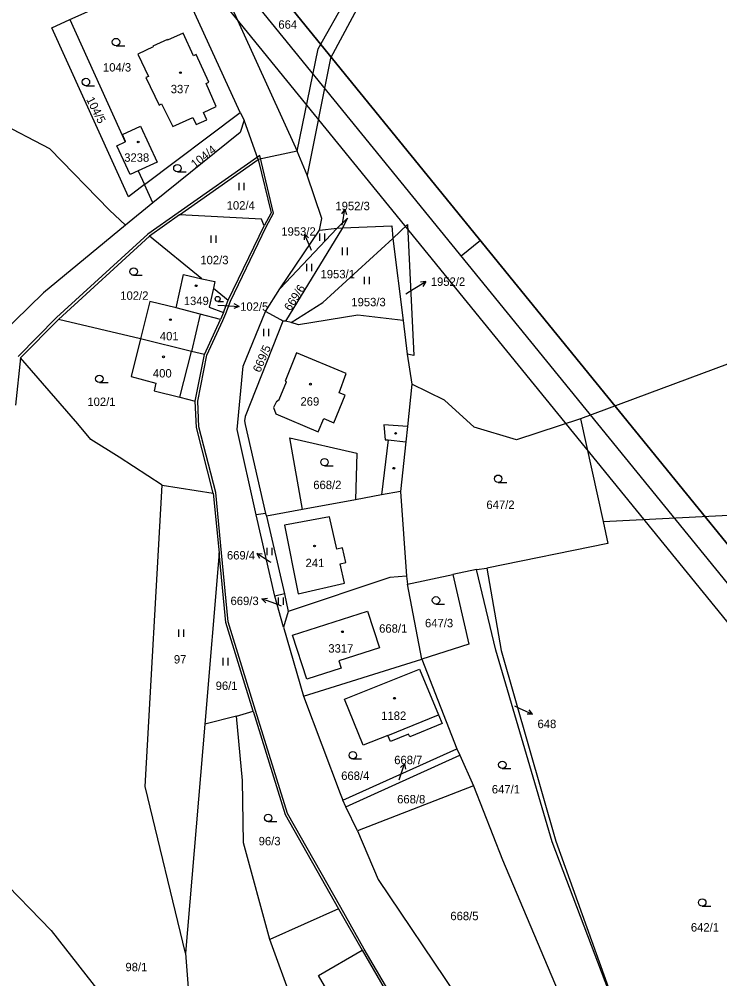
# Model space of a CAD drawing. Extents: x -866656 to -858817, y -1041816 to -1038653.
# Drawn here: x -866089.1 to -865947.5, y -1039508.8 to -1039314.8 of the extents above; entities that cross this region are included whole.
import ezdxf

# ---------------------------------------------------------------- set-up
doc = ezdxf.new("R2010")
doc.units = 0
for name, color, linetype in [('Hranice parcel', 7, 'Continuous'), ('Parcelní čísla', 7, 'Continuous'), ('Pop  PČ popisy', 7, 'Continuous'), ('tisk ramy', 7, 'Continuous'), ('Vnitřní kresba', 7, 'Continuous'), ('Značky budov', 7, 'Continuous'), ('Značky kultur', 7, 'Continuous')]:
    doc.layers.add(name, color=color, linetype=linetype)

msp = doc.modelspace()

# ---------------------------------------------------------------- linework, layer by layer
at = {"layer": 'Hranice parcel'}
for p, q in [((-866028.64, -1039320.79), (-866017.02, -1039299.91)), ((-866078.86, -1039314.87), (-866057.44, -1039305.25)), ((-866044.44, -1039333.64), (-866057.44, -1039305.25)), ((-866048.15, -1039307.93), (-866032.91, -1039341.46)), ((-866019.82, -1039310.81), (-866026.21, -1039322.66)), ((-866082.5, -1039316.53), (-866078.86, -1039314.87)), ((-866078.86, -1039314.87), (-866067.68, -1039339.57)), ((-866067.02, -1039350.71), (-866082.5, -1039316.53)), ((-866059.15, -1039318.92), (-866062.06, -1039320.26)), ((-866059.09, -1039319.05), (-866059.15, -1039318.92)), ((-866055.96, -1039317.6), (-866059.09, -1039319.05)), ((-866053.86, -1039322.16), (-866055.96, -1039317.6)), ((-866061.99, -1039320.4), (-866065.14, -1039321.86)), ((-866062.06, -1039320.26), (-866061.99, -1039320.4)), ((-866032.91, -1039341.46), (-866028.64, -1039320.79)), ((-866065.14, -1039321.86), (-866062.98, -1039326.34)), ((-866053.32, -1039321.92), (-866053.86, -1039322.16)), ((-866050.74, -1039327.52), (-866053.32, -1039321.92)), ((-866026.21, -1039322.66), (-866030.88, -1039346.29)), ((-866062.98, -1039326.34), (-866063.51, -1039326.6)), ((-866063.51, -1039326.6), (-866060.83, -1039332.14)), ((-866051.28, -1039327.77), (-866050.74, -1039327.52)), ((-866049.3, -1039332.42), (-866051.28, -1039327.77)), ((-866082.88, -1039340.97), (-866099.79, -1039332.19)), ((-866060.83, -1039332.14), (-866060.3, -1039331.89)), ((-866060.3, -1039331.89), (-866058.07, -1039336.5)), ((-866051.86, -1039333.68), (-866049.3, -1039332.42)), ((-866063.75, -1039348.24), (-866044.44, -1039333.64)), ((-866051.2, -1039335.12), (-866051.86, -1039333.68)), ((-866044.44, -1039333.64), (-866043.63, -1039335.22)), ((-866058.07, -1039336.5), (-866054, -1039334.65)), ((-866054, -1039334.65), (-866053.34, -1039336.09)), ((-866053.34, -1039336.09), (-866051.2, -1039335.12)), ((-866043.63, -1039335.22), (-866044.44, -1039337.67)), ((-866040.79, -1039343.17), (-866043.63, -1039335.22)), ((-866068.24, -1039338.11), (-866064.58, -1039336.41)), ((-866067.58, -1039339.52), (-866068.24, -1039338.11)), ((-866064.58, -1039336.41), (-866061.23, -1039343.66)), ((-866044.44, -1039337.67), (-866062.09, -1039351.91)), ((-866069.37, -1039340.37), (-866067.68, -1039339.57)), ((-866067.68, -1039339.57), (-866067.58, -1039339.52)), ((-866070.83, -1039353.37), (-866082.88, -1039340.97)), ((-866066.66, -1039346.2), (-866069.37, -1039340.37)), ((-866032.91, -1039341.46), (-866040.79, -1039343.17)), ((-866030.88, -1039346.29), (-866032.91, -1039341.46)), ((-866061.23, -1039343.66), (-866065.02, -1039345.43)), ((-866056.68, -1039354.36), (-866040.79, -1039343.17)), ((-866040.79, -1039343.17), (-866038.2, -1039353.94)), ((-866065.02, -1039345.43), (-866066.66, -1039346.2)), ((-866065.02, -1039345.43), (-866063.75, -1039348.24)), ((-866027.92, -1039355.11), (-866030.88, -1039346.29)), ((-866063.75, -1039348.24), (-866067.02, -1039350.71)), ((-866062.09, -1039351.91), (-866063.75, -1039348.24)), ((-866062.09, -1039351.91), (-866067.64, -1039356.45)), ((-866067.64, -1039356.45), (-866070.83, -1039353.37)), ((-866056.68, -1039354.36), (-866062.78, -1039358.65)), ((-866040.12, -1039355.21), (-866056.68, -1039354.36)), ((-866039.6, -1039356.54), (-866040.12, -1039355.21)), ((-866038.2, -1039353.94), (-866039.6, -1039356.54)), ((-866028.42, -1039357.43), (-866027.92, -1039355.11)), ((-866024.83, -1039357.02), (-866022.74, -1039355.04)), ((-866022.74, -1039355.04), (-866023.78, -1039356.97)), ((-866067.64, -1039356.45), (-866084.17, -1039370.09)), ((-866046.85, -1039371.6), (-866039.6, -1039356.54)), ((-866036.43, -1039369.33), (-866024.83, -1039357.02)), ((-866036.43, -1039369.33), (-866028.42, -1039357.43)), ((-866023.78, -1039356.97), (-866035.26, -1039375.83)), ((-866028.42, -1039357.43), (-866024.83, -1039357.02)), ((-866024.83, -1039357.02), (-866023.78, -1039356.97)), ((-866023.78, -1039356.97), (-866013.77, -1039356.58)), ((-866013.77, -1039356.58), (-866013.6, -1039359.13)), ((-866013.6, -1039359.13), (-866010.65, -1039356.31)), ((-866010.65, -1039356.31), (-866009.31, -1039382.79)), ((-866062.78, -1039358.65), (-866081.18, -1039375.48)), ((-866052.2, -1039367.25), (-866062.78, -1039358.65)), ((-866027.74, -1039372.07), (-866013.6, -1039359.13)), ((-866013.6, -1039359.13), (-866011.48, -1039375.7)), ((-866057.39, -1039373.14), (-866055.87, -1039366.42)), ((-866055.87, -1039366.42), (-866052.2, -1039367.25)), ((-866052.2, -1039367.25), (-866049.54, -1039367.85)), ((-866049.84, -1039369.17), (-866050.71, -1039373.02)), ((-866049.54, -1039367.85), (-866049.84, -1039369.17)), ((-866049.84, -1039369.17), (-866046.85, -1039371.6)), ((-866039.34, -1039373.88), (-866036.43, -1039369.33)), ((-866084.17, -1039370.09), (-866092.99, -1039378.67)), ((-866062.69, -1039371.86), (-866064.59, -1039379.4)), ((-866057.39, -1039373.14), (-866062.69, -1039371.86)), ((-866052.54, -1039374.42), (-866057.39, -1039373.14)), ((-866050.71, -1039373.02), (-866047.83, -1039374.11)), ((-866047.83, -1039374.11), (-866046.85, -1039371.6)), ((-866034.12, -1039376.14), (-866027.74, -1039372.07)), ((-866048.39, -1039375.52), (-866052.54, -1039374.42)), ((-866047.83, -1039374.11), (-866048.39, -1039375.52)), ((-866043.85, -1039384.96), (-866039.34, -1039373.88)), ((-866036.22, -1039375.56), (-866039.34, -1039373.88)), ((-866020.66, -1039374.6), (-866032.67, -1039376.55)), ((-866011.48, -1039375.7), (-866020.66, -1039374.6)), ((-866081.18, -1039375.48), (-866088.85, -1039383.25)), ((-866064.59, -1039379.4), (-866081.18, -1039375.48)), ((-866051.65, -1039382.56), (-866048.39, -1039375.52)), ((-866035.78, -1039375.84), (-866043.4, -1039395.11)), ((-866035.78, -1039375.84), (-866036.22, -1039375.56)), ((-866035.26, -1039375.83), (-866035.78, -1039375.84)), ((-866034.12, -1039376.14), (-866035.26, -1039375.83)), ((-866032.67, -1039376.55), (-866034.12, -1039376.14)), ((-866011.48, -1039375.7), (-866010.7, -1039382.53)), ((-865926.41, -1039377.21), (-865975.66, -1039395.58)), ((-866064.59, -1039379.4), (-866066.46, -1039387.06)), ((-866054.3, -1039382), (-866064.59, -1039379.4)), ((-866051.65, -1039382.56), (-866054.3, -1039382)), ((-866053.52, -1039392), (-866051.65, -1039382.56)), ((-866010.7, -1039382.53), (-866009.76, -1039388.61)), ((-866009.31, -1039382.79), (-866010.7, -1039382.53)), ((-866088.85, -1039383.25), (-866089.81, -1039392.85)), ((-866077.27, -1039396.58), (-866088.85, -1039383.25)), ((-866045.07, -1039397.73), (-866043.85, -1039384.96)), ((-866066.46, -1039387.06), (-866061.45, -1039388.35)), ((-866061.45, -1039388.35), (-866061.84, -1039389.95)), ((-866009.76, -1039388.61), (-866010.64, -1039397.17)), ((-866003.13, -1039391.81), (-866009.76, -1039388.61)), ((-866061.84, -1039389.95), (-866056.6, -1039391.24)), ((-866056.6, -1039391.24), (-866053.52, -1039392)), ((-866053.28, -1039397.31), (-866053.52, -1039392)), ((-865997.15, -1039397.26), (-866003.13, -1039391.81)), ((-866043.4, -1039395.11), (-866043.53, -1039396.02)), ((-866043.53, -1039396.02), (-866043.42, -1039396.72)), ((-865975.66, -1039395.58), (-865988.57, -1039399.82)), ((-865975.66, -1039395.58), (-865971.07, -1039416.36)), ((-866074.59, -1039399.75), (-866077.27, -1039396.58)), ((-866049.86, -1039410.61), (-866053.28, -1039397.31)), ((-866041.17, -1039415.01), (-866045.07, -1039397.73)), ((-866043.42, -1039396.72), (-866039.34, -1039414.72)), ((-866010.64, -1039397.17), (-866010.96, -1039400.24)), ((-865988.57, -1039399.82), (-865997.15, -1039397.26)), ((-866068.91, -1039403.37), (-866074.59, -1039399.75)), ((-866031.82, -1039413.91), (-866034.38, -1039399.43)), ((-866034.38, -1039399.43), (-866020.85, -1039402.53)), ((-866010.96, -1039400.24), (-866012, -1039410.29)), ((-866060.2, -1039409.03), (-866068.91, -1039403.37)), ((-866020.85, -1039402.53), (-866021.15, -1039411.96)), ((-866063.61, -1039469.96), (-866060.2, -1039409.03)), ((-866060.2, -1039409.03), (-866049.86, -1039410.61)), ((-866049.86, -1039410.61), (-866048.7, -1039422.71)), ((-866021.15, -1039411.96), (-866031.82, -1039413.91)), ((-866015.86, -1039410.99), (-866021.15, -1039411.96)), ((-866012, -1039410.29), (-866015.86, -1039410.99)), ((-866012, -1039410.29), (-866010.83, -1039427.42)), ((-866031.82, -1039413.91), (-866039.14, -1039415.25)), ((-866039.34, -1039414.72), (-866041.17, -1039415.01)), ((-866037.45, -1039431.46), (-866041.17, -1039415.01)), ((-866039.34, -1039414.72), (-866039.14, -1039415.25)), ((-866039.14, -1039415.25), (-866035.5, -1039431)), ((-865971.07, -1039416.36), (-865942.36, -1039414.92)), ((-865971.07, -1039416.36), (-865970.13, -1039420.81)), ((-865970.13, -1039420.81), (-865994.6, -1039425.76)), ((-866048.7, -1039422.71), (-866051.6, -1039457.36)), ((-866047.36, -1039436.76), (-866048.7, -1039422.71)), ((-866010.83, -1039427.42), (-866014.16, -1039427.65)), ((-866010.83, -1039427.42), (-866010.62, -1039428.99)), ((-866010.62, -1039428.99), (-866001.47, -1039427.05)), ((-865996.64, -1039426.09), (-866001.47, -1039427.05)), ((-866001.47, -1039427.05), (-865998.21, -1039441.16)), ((-865996.64, -1039426.09), (-865994.6, -1039425.76)), ((-865992.79, -1039442.34), (-865996.64, -1039426.09)), ((-865994.6, -1039425.76), (-865991.69, -1039442.44)), ((-866014.16, -1039427.65), (-866034.75, -1039434.55)), ((-866007.74, -1039444.16), (-866010.62, -1039428.99)), ((-866035.5, -1039431), (-866037.45, -1039431.46)), ((-866035.7, -1039437.72), (-866037.45, -1039431.46)), ((-866035.5, -1039431), (-866034.75, -1039434.55)), ((-866034.75, -1039434.55), (-866035.7, -1039437.72)), ((-866033.87, -1039439.32), (-866018.68, -1039434.45)), ((-866018.68, -1039434.45), (-866016.28, -1039441.91)), ((-866041.79, -1039454.72), (-866047.36, -1039436.76)), ((-866035.7, -1039437.72), (-866031.66, -1039451.67)), ((-866030.97, -1039448.25), (-866033.87, -1039439.32)), ((-865998.21, -1039441.16), (-866007.74, -1039444.16)), ((-866016.28, -1039441.91), (-866024.49, -1039444.54)), ((-865981.41, -1039481.1), (-865992.79, -1039442.34)), ((-865991.69, -1039442.44), (-865980.64, -1039480.99)), ((-866031.66, -1039451.67), (-866007.74, -1039444.16)), ((-866024.49, -1039444.54), (-866024, -1039446.04)), ((-866007.74, -1039444.16), (-866000.62, -1039462.33)), ((-866024, -1039446.04), (-866030.97, -1039448.25)), ((-866023.32, -1039452.25), (-866008.18, -1039446.19)), ((-866008.18, -1039446.19), (-866004.36, -1039455.42)), ((-866031.66, -1039451.67), (-866024.24, -1039471.38)), ((-866019.6, -1039461.57), (-866023.32, -1039452.25)), ((-866045.19, -1039455.72), (-866041.79, -1039454.72)), ((-866041.79, -1039454.72), (-866035.32, -1039475.58)), ((-866045.19, -1039455.72), (-866051.6, -1039457.36)), ((-866043.98, -1039468.75), (-866045.19, -1039455.72)), ((-866004.36, -1039455.42), (-866003.63, -1039457.17)), ((-866051.6, -1039457.36), (-866055.47, -1039503.65)), ((-866003.63, -1039457.17), (-866010.16, -1039459.88)), ((-866014.57, -1039459.65), (-866019.6, -1039461.57)), ((-866014.08, -1039460.86), (-866014.57, -1039459.65)), ((-866010.39, -1039459.32), (-866014.08, -1039460.86)), ((-866010.16, -1039459.88), (-866010.39, -1039459.32)), ((-866023.7, -1039472.72), (-866000.62, -1039462.33)), ((-866000.62, -1039462.33), (-866000.05, -1039463.61)), ((-866023.06, -1039474.02), (-866000.05, -1039463.61)), ((-866000.05, -1039463.61), (-865997.28, -1039469.79)), ((-866055.47, -1039503.65), (-866063.61, -1039469.96)), ((-866043.78, -1039481.33), (-866043.98, -1039468.75)), ((-865997.28, -1039469.79), (-866020.75, -1039478.89)), ((-865997.28, -1039469.79), (-865991.39, -1039484.77)), ((-866024.24, -1039471.38), (-866023.7, -1039472.72)), ((-866023.06, -1039474.02), (-866023.7, -1039472.72)), ((-866020.75, -1039478.89), (-866023.06, -1039474.02)), ((-866035.32, -1039475.58), (-866024.54, -1039494.65)), ((-866020.75, -1039478.89), (-866016.56, -1039488.74)), ((-866038.46, -1039500.9), (-866043.78, -1039481.33)), ((-865966.62, -1039519.96), (-865981.41, -1039481.1)), ((-865980.64, -1039480.99), (-865966.62, -1039519.96)), ((-866098.59, -1039482.64), (-866082.64, -1039499.05)), ((-865991.39, -1039484.77), (-865980.2, -1039511.37)), ((-866016.56, -1039488.74), (-866000.82, -1039512.05)), ((-866024.54, -1039494.65), (-866038.46, -1039500.9)), ((-866024.54, -1039494.65), (-866019.79, -1039503.06)), ((-866082.64, -1039499.05), (-866055.31, -1039533.99)), ((-866033.4, -1039514.72), (-866038.46, -1039500.9)), ((-866019.79, -1039503.06), (-866013.06, -1039514.58)), ((-866055.47, -1039503.65), (-866053.67, -1039527.47))]:
    msp.add_line(p, q, dxfattribs=at)
at = {"layer": 'Pop  PČ popisy'}
for p, q in [((-866023.28, -1039353.22), (-866023.93, -1039354.13)), ((-866023.75, -1039356.18), (-866023.28, -1039353.22)), ((-866023.28, -1039353.22), (-866022.94, -1039354.28)), ((-866023.79, -1039356.41), (-866023.75, -1039356.18)), ((-866031.46, -1039358.27), (-866031.51, -1039359.39)), ((-866030.24, -1039361.01), (-866031.46, -1039358.27)), ((-866031.46, -1039358.27), (-866030.6, -1039358.98)), ((-866030, -1039361.55), (-866030.24, -1039361.01)), ((-866009.48, -1039369.4), (-866006.91, -1039367.85)), ((-866006.91, -1039367.85), (-866008.02, -1039367.94)), ((-866006.91, -1039367.85), (-866007.51, -1039368.8)), ((-866010.95, -1039370.29), (-866009.48, -1039369.4)), ((-866048.97, -1039372.63), (-866047.67, -1039372.7)), ((-866047.67, -1039372.7), (-866044.67, -1039372.86)), ((-866044.67, -1039372.86), (-866045.7, -1039373.31)), ((-866044.67, -1039372.86), (-866045.65, -1039372.31)), ((-866038.57, -1039424.42), (-866041.09, -1039422.79)), ((-866041.09, -1039422.79), (-866039.97, -1039422.91)), ((-866041.09, -1039422.79), (-866040.52, -1039423.75)), ((-866038.2, -1039424.66), (-866038.57, -1039424.42)), ((-866040.04, -1039431.99), (-866038.93, -1039431.87)), ((-866037.22, -1039433.02), (-866040.04, -1039431.99)), ((-866040.04, -1039431.99), (-866039.27, -1039432.81)), ((-866036.08, -1039433.44), (-866037.22, -1039433.02)), ((-865989, -1039453.65), (-865988.07, -1039454.07)), ((-865988.07, -1039454.07), (-865985.33, -1039455.29)), ((-865985.33, -1039455.29), (-865986.04, -1039454.43)), ((-865985.33, -1039455.29), (-865986.45, -1039455.34)), ((-866012.14, -1039468.17), (-866011.21, -1039465.32)), ((-866011.21, -1039465.32), (-866012, -1039466.11)), ((-866011.21, -1039465.32), (-866011.05, -1039466.42)), ((-866012.28, -1039468.62), (-866012.14, -1039468.17))]:
    msp.add_line(p, q, dxfattribs=at)
at = {"layer": 'tisk ramy'}
msp.add_line((-865995.88, -1039359.55), (-865999.76, -1039362.7), dxfattribs=at)
for points in [[(-866268.65, -1039040.03), (-865473.6, -1040017.5), (-865243.2, -1039830.1), (-866038.25, -1038852.63)], [(-866038.97, -1038859.66), (-865250.23, -1039829.38), (-865472.87, -1040010.47), (-866261.62, -1039040.75)], [(-866254.59, -1039041.47), (-865601.5, -1039844.41), (-865386.61, -1039669.62), (-866039.7, -1038866.69)], [(-866039.7, -1038866.69), (-865386.61, -1039669.62), (-865601.5, -1039844.41), (-866254.59, -1039041.47)]]:
    msp.add_lwpolyline(points, close=True, dxfattribs=at)
at = {"layer": 'Vnitřní kresba'}
for p, q in [((-866040.48, -1039342.34), (-866056.97, -1039353.95)), ((-866037.67, -1039354.01), (-866040.48, -1039342.34)), ((-866056.97, -1039353.95), (-866063.09, -1039358.26)), ((-866039.15, -1039356.77), (-866037.67, -1039354.01)), ((-866046.39, -1039371.8), (-866039.15, -1039356.77)), ((-866063.09, -1039358.26), (-866081.53, -1039375.12)), ((-866047.36, -1039374.29), (-866046.39, -1039371.8)), ((-866081.53, -1039375.12), (-866089.33, -1039383.02)), ((-866052.54, -1039374.42), (-866054.3, -1039382)), ((-866047.93, -1039375.72), (-866047.36, -1039374.29)), ((-866051.17, -1039382.72), (-866047.93, -1039375.72)), ((-866056.6, -1039391.24), (-866054.3, -1039382)), ((-866053.02, -1039392.04), (-866051.17, -1039382.72)), ((-866033.06, -1039382.27), (-866035.36, -1039387.97)), ((-866023.01, -1039386.4), (-866033.06, -1039382.27)), ((-866024.42, -1039390.32), (-866023.01, -1039386.4)), ((-866036.56, -1039391.7), (-866035.08, -1039388.09)), ((-866035.36, -1039387.97), (-866035.08, -1039388.09)), ((-866023.22, -1039390.8), (-866024.42, -1039390.32)), ((-866052.78, -1039397.24), (-866053.02, -1039392.04)), ((-866037.1, -1039392.06), (-866037.69, -1039393.27)), ((-866037.1, -1039392.06), (-866036.56, -1039391.7)), ((-866025.51, -1039396.38), (-866023.22, -1039390.8)), ((-866037.69, -1039393.27), (-866037.22, -1039394.55)), ((-866037.22, -1039394.55), (-866028.65, -1039398.25)), ((-866028.65, -1039398.25), (-866027.54, -1039395.54)), ((-866027.54, -1039395.54), (-866025.51, -1039396.38)), ((-866049.37, -1039410.52), (-866052.78, -1039397.24)), ((-866015.37, -1039396.82), (-866015.12, -1039399.81)), ((-866010.64, -1039397.17), (-866015.37, -1039396.82)), ((-866014.5, -1039399.87), (-866015.86, -1039410.99)), ((-866015.12, -1039399.81), (-866014.5, -1039399.87)), ((-866014.5, -1039399.87), (-866010.96, -1039400.24)), ((-866048.2, -1039422.66), (-866049.37, -1039410.52)), ((-866026.41, -1039415.43), (-866035.5, -1039417.06)), ((-866024.92, -1039421.92), (-866026.41, -1039415.43)), ((-866035.5, -1039417.06), (-866032.69, -1039431.01)), ((-866023.75, -1039421.65), (-866024.92, -1039421.92)), ((-866023.06, -1039424.67), (-866023.75, -1039421.65)), ((-866046.87, -1039436.66), (-866048.2, -1039422.66)), ((-866024.23, -1039424.94), (-866023.06, -1039424.67)), ((-866023.33, -1039428.84), (-866024.23, -1039424.94)), ((-866032.69, -1039431.01), (-866023.33, -1039428.84)), ((-866041.31, -1039454.57), (-866046.87, -1039436.66)), ((-866034.86, -1039475.38), (-866041.31, -1039454.57)), ((-866014.57, -1039459.65), (-866004.36, -1039455.42)), ((-866024.1, -1039494.4), (-866034.86, -1039475.38)), ((-866019.36, -1039502.81), (-866024.1, -1039494.4)), ((-866028.62, -1039508.13), (-866019.79, -1039503.06)), ((-866012.6, -1039514.29), (-866019.36, -1039502.81)), ((-866026.19, -1039512.33), (-866028.62, -1039508.13))]:
    msp.add_line(p, q, dxfattribs=at)
at = {"layer": 'Značky budov'}
for centre in [(-866056.5, -1039325.59), (-866065.04, -1039339.61), (-866053.33, -1039368.69), (-866058.53, -1039375.55), (-866059.93, -1039383.06), (-866030.24, -1039388.58), (-866013.01, -1039398.53), (-866013.38, -1039405.58), (-866029.4, -1039421.3), (-866023.77, -1039438.65), (-866013.24, -1039452.09)]:
    msp.add_circle(centre, 0.175, dxfattribs=at)
at = {"layer": 'Značky kultur'}
for p, q in [((-866069.52, -1039320.16), (-866067.77, -1039320.16)), ((-866075.6, -1039328.23), (-866073.85, -1039328.23)), ((-866057.12, -1039345.67), (-866055.37, -1039345.67)), ((-866044.64, -1039349.34), (-866044.64, -1039347.84)), ((-866043.64, -1039349.34), (-866043.64, -1039347.84)), ((-866050.27, -1039360.03), (-866050.27, -1039358.53)), ((-866049.27, -1039360.03), (-866049.27, -1039358.53)), ((-866028.31, -1039359.59), (-866028.31, -1039358.09)), ((-866027.31, -1039359.59), (-866027.31, -1039358.09)), ((-866023.75, -1039362.47), (-866023.75, -1039360.97)), ((-866022.75, -1039362.47), (-866022.75, -1039360.97)), ((-866030.93, -1039365.72), (-866030.93, -1039364.22)), ((-866029.93, -1039365.72), (-866029.93, -1039364.22)), ((-866065.96, -1039366.57), (-866064.21, -1039366.57)), ((-866019.28, -1039368.36), (-866019.28, -1039366.86)), ((-866018.28, -1039368.36), (-866018.28, -1039366.86)), ((-866048.98, -1039371.85), (-866047.81, -1039371.85)), ((-866039.62, -1039378.87), (-866039.62, -1039377.37)), ((-866038.62, -1039378.87), (-866038.62, -1039377.37)), ((-866072.89, -1039388.26), (-866071.14, -1039388.26)), ((-866027.4, -1039405.1), (-866025.65, -1039405.1)), ((-865992.3, -1039408.45), (-865990.55, -1039408.45)), ((-866038.96, -1039423.15), (-866038.96, -1039421.65)), ((-866037.96, -1039423.15), (-866037.96, -1039421.65)), ((-866036.67, -1039433.22), (-866036.67, -1039431.72)), ((-866035.67, -1039433.22), (-866035.67, -1039431.72)), ((-866004.86, -1039433.04), (-866003.11, -1039433.04)), ((-866056.82, -1039439.68), (-866056.82, -1039438.18)), ((-866055.82, -1039439.68), (-866055.82, -1039438.18)), ((-866047.88, -1039445.45), (-866047.88, -1039443.95)), ((-866046.88, -1039445.45), (-866046.88, -1039443.95)), ((-866021.66, -1039464.37), (-866019.91, -1039464.37)), ((-865991.46, -1039466.29), (-865989.71, -1039466.29)), ((-866038.78, -1039477.04), (-866037.03, -1039477.04)), ((-865951.05, -1039494.13), (-865949.3, -1039494.13))]:
    msp.add_line(p, q, dxfattribs=at)
for centre, radius in [((-866069.52, -1039319.41), 0.75), ((-866075.6, -1039327.48), 0.75), ((-866057.12, -1039344.92), 0.75), ((-866065.96, -1039365.82), 0.75), ((-866048.99, -1039371.35), 0.502), ((-866072.89, -1039387.51), 0.75), ((-866027.4, -1039404.35), 0.75), ((-865992.3, -1039407.7), 0.75), ((-866004.86, -1039432.29), 0.75), ((-866021.66, -1039463.62), 0.75), ((-865991.46, -1039465.54), 0.75), ((-866038.78, -1039476.29), 0.75), ((-865951.05, -1039493.38), 0.75)]:
    msp.add_circle(centre, radius, dxfattribs=at)

# ---------------------------------------------------------------- texts
at = {"layer": 'Parcelní čísla'}
for s, p in [('664', (-866036.72, -1039316.71)), ('104/3', (-866072.16, -1039325.37)), ('337', (-866058.46, -1039329.76)), ('3238', (-866067.87, -1039343.61)), ('102/4', (-866047.16, -1039353.28)), ('1952/3', (-866025.19, -1039353.4)), ('1953/2', (-866036.12, -1039358.56)), ('102/3', (-866052.48, -1039364.33)), ('1953/1', (-866028.19, -1039367.18)), ('1952/2', (-866005.91, -1039368.7)), ('102/2', (-866068.66, -1039371.52)), ('1349', (-866055.83, -1039372.59)), ('1953/3', (-866021.97, -1039372.83)), ('102/5', (-866044.44, -1039373.74)), ('401', (-866060.67, -1039379.72)), ('400', (-866062.07, -1039387.23)), ('102/1', (-866075.31, -1039392.99)), ('269', (-866032.25, -1039392.92)), ('668/2', (-866029.66, -1039409.8)), ('647/2', (-865994.67, -1039413.82)), ('669/4', (-866047.11, -1039424.03)), ('241', (-866031.22, -1039425.58)), ('669/3', (-866046.38, -1039433.25)), ('668/1', (-866016.35, -1039438.83)), ('647/3', (-866007.08, -1039437.74)), ('3317', (-866026.62, -1039442.86)), ('97', (-866057.83, -1039445.06)), ('96/1', (-866049.39, -1039450.41)), ('1182', (-866015.93, -1039456.47)), ('648', (-865984.34, -1039458.13)), ('668/7', (-866013.3, -1039465.42)), ('668/4', (-866024.02, -1039468.6)), ('647/1', (-865993.58, -1039471.34)), ('668/8', (-866012.71, -1039473.35)), ('96/3', (-866040.7, -1039481.83)), ('668/5', (-866001.96, -1039496.97)), ('642/1', (-865953.35, -1039499.26)), ('98/1', (-866067.62, -1039507.29))]:
    msp.add_text(s, height=1.7, dxfattribs=at).set_placement(p)
for s, rotation, p in [('104/5', 297, (-866075.6, -1039331)), ('104/4', 38, (-866053.57, -1039344.99)), ('669/6', 57, (-866034.28, -1039373.93)), ('669/5', 67, (-866040.4, -1039386.36))]:
    msp.add_text(s, height=1.7, rotation=rotation, dxfattribs=at).set_placement(p)

doc.saveas('drawing.dxf')
